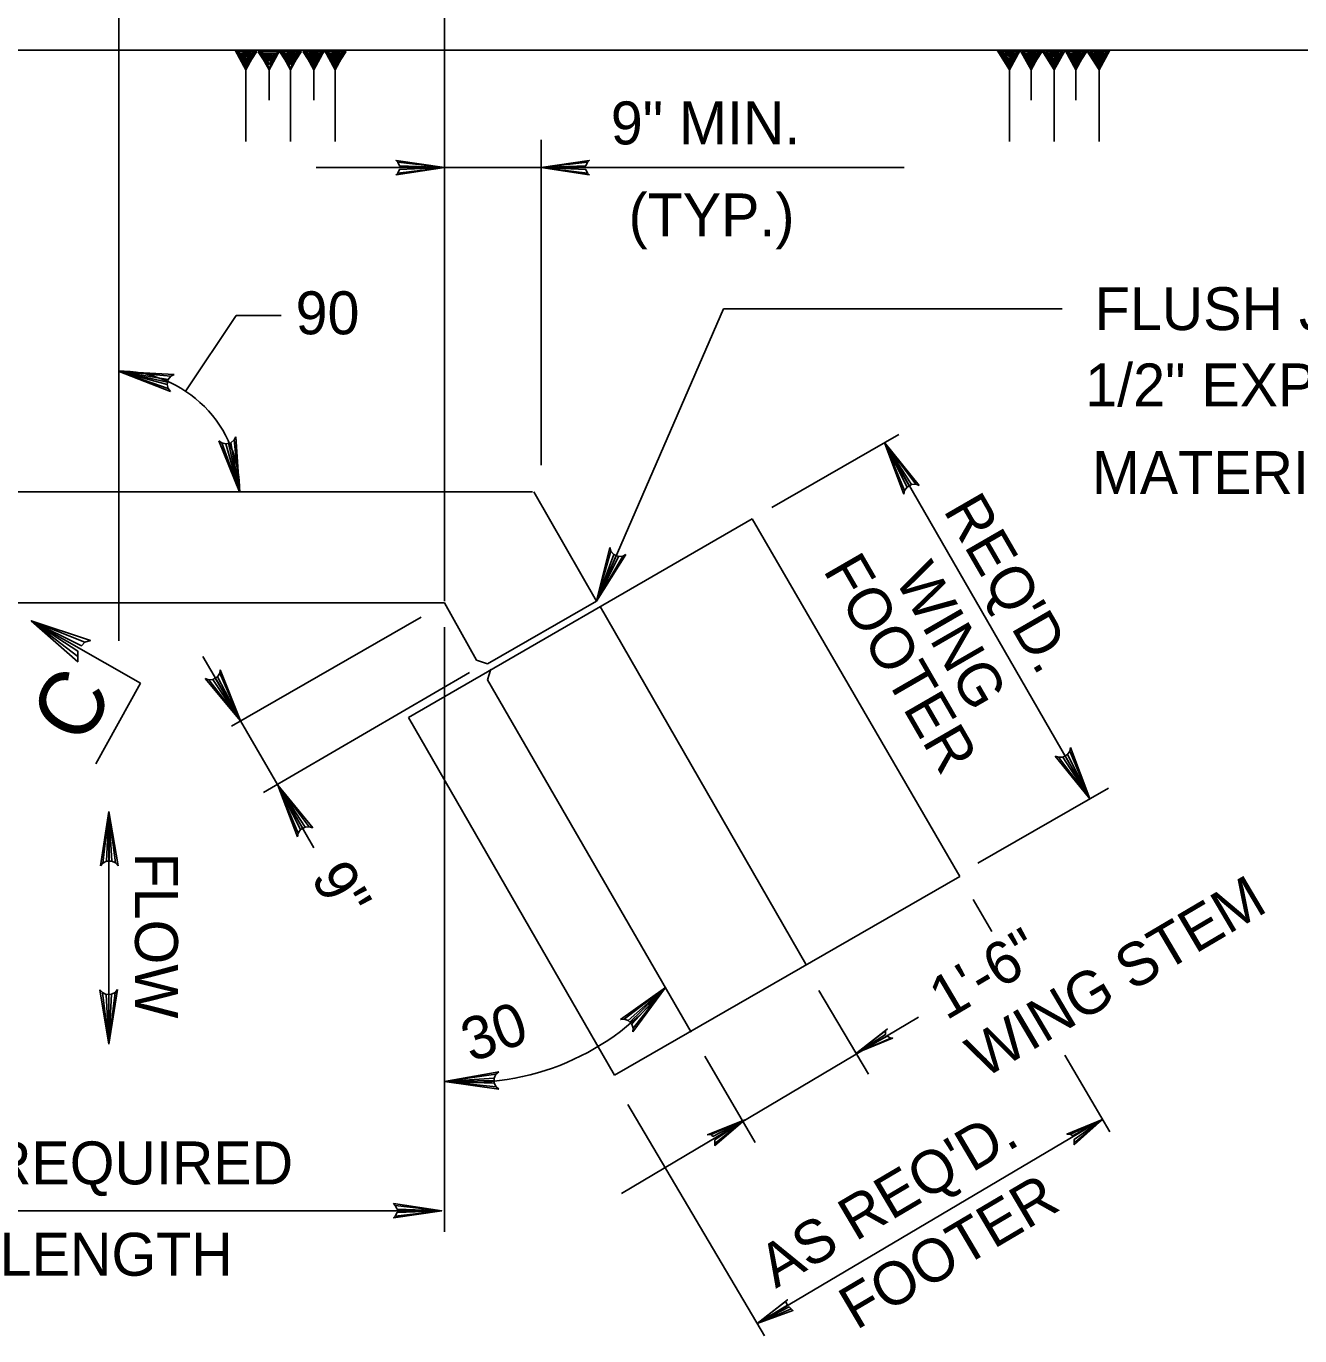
# Model space of a CAD drawing. Extents: x 639011 to 639866, y 298840 to 300028.
# Drawn here: x 639208.9 to 639297.8, y 299878.8 to 299970.3 of the extents above; entities that cross this region are included whole.
import ezdxf

# ---------------------------------------------------------------- set-up
doc = ezdxf.new("R2010")
doc.units = 0
doc.layers.add('2', color=7, linetype='Continuous')

msp = doc.modelspace()

# ---------------------------------------------------------------- linework, layer by layer
at = {"layer": '2'}
for p, q in [((639215.32, 299927.334), (639215.32, 300000.662)), ((639238.07, 299937.353), (639238.07, 299976.728)), ((639238.07, 299937.353), (639238.07, 299976.728)), ((639153.945, 299968.603), (639239.07, 299968.603)), ((639164.418, 299968.603), (639305.616, 299968.603)), ((639224.195, 299967.228), (639224.195, 299962.228)), ((639225.82, 299967.228), (639225.82, 299965.103)), ((639227.32, 299967.228), (639227.32, 299962.228)), ((639228.945, 299967.228), (639228.945, 299965.103)), ((639230.445, 299967.228), (639230.445, 299962.228)), ((639277.551, 299967.228), (639277.551, 299962.228)), ((639279.051, 299967.228), (639279.051, 299965.103)), ((639280.676, 299967.228), (639280.676, 299962.228)), ((639282.176, 299967.228), (639282.176, 299965.103)), ((639283.801, 299967.228), (639283.801, 299962.228)), ((639244.82, 299939.603), (639244.82, 299962.344)), ((639270.195, 299960.392), (639229.109, 299960.392)), ((639248.695, 299930.103), (639257.562, 299950.524)), ((639257.562, 299950.524), (639281.233, 299950.524)), ((639220.019, 299944.792), (639223.529, 299950.07)), ((639223.529, 299950.07), (639226.675, 299950.07)), ((639238.07, 299938.353), (639238.07, 299946.728)), ((639238.07, 299938.353), (639238.07, 299946.728)), ((639218.699, 299945.236), (639215.346, 299946.156)), ((639215.346, 299946.156), (639218.774, 299944.947)), ((639218.927, 299944.749), (639215.346, 299946.156)), ((639215.346, 299946.156), (639218.776, 299945.589)), ((639218.958, 299945.817), (639215.346, 299946.156)), ((639215.346, 299946.156), (639219.187, 299945.946)), ((639215.346, 299946.156), (639218.738, 299945.412)), ((639218.776, 299945.589), (639218.958, 299945.817)), ((639219.187, 299945.946), (639218.958, 299945.817)), ((639218.699, 299945.236), (639218.776, 299945.589)), ((639218.774, 299944.947), (639218.699, 299945.236)), ((639218.774, 299944.947), (639218.927, 299944.749)), ((639223.762, 299937.748), (639222.303, 299941.308)), ((639222.303, 299941.308), (639222.518, 299941.156)), ((639223.382, 299941.363), (639223.154, 299941.172)), ((639223.382, 299941.363), (639223.495, 299941.586)), ((639223.762, 299937.748), (639223.382, 299941.363)), ((639223.495, 299941.586), (639223.762, 299937.748)), ((639260.952, 299936.65), (639269.815, 299941.747)), ((639222.802, 299941.09), (639222.518, 299941.156)), ((639222.518, 299941.156), (639223.762, 299937.748)), ((639223.154, 299941.172), (639222.802, 299941.09)), ((639223.762, 299937.748), (639222.802, 299941.09)), ((639223.762, 299937.748), (639222.978, 299941.131)), ((639223.154, 299941.172), (639223.762, 299937.748)), ((639270.701, 299938.25), (639268.826, 299941.178)), ((639268.826, 299941.178), (639270.998, 299938.264)), ((639271.233, 299938.177), (639268.826, 299941.178)), ((639268.826, 299941.178), (639270.387, 299938.071)), ((639270.223, 299937.83), (639268.826, 299941.178)), ((639268.826, 299941.178), (639270.167, 299937.573)), ((639268.826, 299941.178), (639270.544, 299938.16)), ((639268.826, 299941.178), (639283.149, 299916.274)), ((639186.57, 299937.728), (639244.219, 299937.728)), ((639244.32, 299937.728), (639248.695, 299930.103)), ((639244.32, 299937.728), (639248.695, 299930.103)), ((639270.167, 299937.573), (639270.223, 299937.83)), ((639270.387, 299938.071), (639270.223, 299937.83)), ((639270.701, 299938.25), (639270.387, 299938.071)), ((639270.998, 299938.264), (639270.701, 299938.25)), ((639270.998, 299938.264), (639271.233, 299938.177)), ((639238.07, 299930.103), (639238.07, 299937.353)), ((639238.07, 299930.103), (639238.07, 299937.353)), ((639235.57, 299921.978), (639259.57, 299935.853)), ((639259.57, 299935.853), (639274.07, 299910.853)), ((639248.695, 299930.103), (639249.624, 299933.836)), ((639249.708, 299933.586), (639248.695, 299930.103)), ((639248.695, 299930.103), (639249.898, 299933.365)), ((639250.75, 299933.355), (639248.695, 299930.103)), ((639248.695, 299930.103), (639250.064, 299933.294)), ((639248.695, 299930.103), (639250.527, 299933.242)), ((639250.23, 299933.223), (639248.695, 299930.103)), ((639249.624, 299933.836), (639249.708, 299933.586)), ((639249.898, 299933.365), (639249.708, 299933.586)), ((639250.23, 299933.223), (639249.898, 299933.365)), ((639250.527, 299933.242), (639250.23, 299933.223)), ((639250.527, 299933.242), (639250.75, 299933.355)), ((639192.695, 299929.978), (639238.07, 299929.978)), ((639238.07, 299929.978), (639240.32, 299925.978)), ((639238.07, 299929.978), (639240.32, 299925.978)), ((639241.07, 299925.728), (639248.695, 299930.103)), ((639241.07, 299925.728), (639248.695, 299930.103)), ((639248.945, 299929.728), (639263.32, 299904.728)), ((639216.837, 299924.358), (639209.212, 299928.733)), ((639223.195, 299921.353), (639236.445, 299928.978)), ((639238.07, 299928.274), (639238.07, 299886.029)), ((639221.195, 299926.228), (639223.82, 299921.728)), ((639240.32, 299925.978), (639241.07, 299925.728)), ((639240.32, 299925.978), (639241.07, 299925.728)), ((639222.213, 299924.812), (639221.902, 299924.627)), ((639223.82, 299921.728), (639222.057, 299924.72)), ((639222.373, 299925.062), (639222.213, 299924.812)), ((639222.213, 299924.812), (639223.82, 299921.728)), ((639222.373, 299925.062), (639222.414, 299925.309)), ((639223.82, 299921.728), (639222.373, 299925.062)), ((639222.414, 299925.309), (639223.82, 299921.728)), ((639225.445, 299916.728), (639239.82, 299925.103)), ((639241.07, 299924.603), (639241.32, 299925.353)), ((639241.07, 299924.603), (639241.32, 299925.353)), ((639216.837, 299924.358), (639213.712, 299918.733)), ((639223.82, 299921.728), (639221.36, 299924.686)), ((639221.36, 299924.686), (639221.611, 299924.605)), ((639221.902, 299924.627), (639221.611, 299924.605)), ((639221.611, 299924.605), (639223.82, 299921.728)), ((639223.82, 299921.728), (639221.902, 299924.627)), ((639241.07, 299924.603), (639255.32, 299899.978)), ((639235.57, 299921.978), (639249.945, 299896.978)), ((639223.82, 299921.728), (639226.445, 299917.228)), ((639280.977, 299919.188), (639280.742, 299919.275)), ((639280.742, 299919.275), (639283.149, 299916.274)), ((639281.274, 299919.202), (639281.589, 299919.38)), ((639283.149, 299916.274), (639281.431, 299919.291)), ((639281.589, 299919.38), (639281.752, 299919.621)), ((639283.149, 299916.274), (639281.589, 299919.38)), ((639281.807, 299919.879), (639281.752, 299919.621)), ((639281.752, 299919.621), (639283.149, 299916.274)), ((639283.149, 299916.274), (639281.807, 299919.879)), ((639280.977, 299919.188), (639281.274, 299919.202)), ((639283.149, 299916.274), (639280.977, 299919.188)), ((639281.274, 299919.202), (639283.149, 299916.274)), ((639226.445, 299917.228), (639228.945, 299912.853)), ((639228.024, 299914.13), (639226.445, 299917.228)), ((639226.445, 299917.228), (639227.862, 299913.881)), ((639227.819, 299913.634), (639226.445, 299917.228)), ((639226.445, 299917.228), (639228.337, 299914.311)), ((639228.628, 299914.331), (639226.445, 299917.228)), ((639226.445, 299917.228), (639228.878, 299914.248)), ((639226.445, 299917.228), (639228.181, 299914.221)), ((639275.337, 299911.78), (639284.455, 299917.024)), ((639214.049, 299911.597), (639214.64, 299915.399)), ((639214.64, 299915.399), (639214.209, 299911.79)), ((639214.474, 299911.926), (639214.64, 299915.399)), ((639214.64, 299899.149), (639214.64, 299915.399)), ((639214.64, 299915.399), (639214.836, 299911.928)), ((639215.098, 299911.801), (639214.64, 299915.399)), ((639214.64, 299915.399), (639215.274, 299911.605)), ((639214.64, 299915.399), (639214.655, 299911.927)), ((639227.862, 299913.881), (639227.819, 299913.634)), ((639227.862, 299913.881), (639228.024, 299914.13)), ((639228.024, 299914.13), (639228.337, 299914.311)), ((639228.337, 299914.311), (639228.628, 299914.331)), ((639228.878, 299914.248), (639228.628, 299914.331)), ((639214.209, 299911.79), (639214.474, 299911.926)), ((639214.474, 299911.926), (639214.836, 299911.928)), ((639214.836, 299911.928), (639215.098, 299911.801)), ((639214.209, 299911.79), (639214.049, 299911.597)), ((639215.274, 299911.605), (639215.098, 299911.801)), ((639249.945, 299896.978), (639274.07, 299910.853)), ((639275.018, 299909.242), (639276.324, 299907.02)), ((639214.64, 299899.149), (639214.005, 299902.944)), ((639214.005, 299902.944), (639214.182, 299902.748)), ((639215.23, 299902.951), (639214.64, 299899.149)), ((639214.64, 299899.149), (639215.07, 299902.759)), ((639215.07, 299902.759), (639214.805, 299902.623)), ((639215.07, 299902.759), (639215.23, 299902.951)), ((639250.374, 299900.873), (639253.509, 299903.103)), ((639253.509, 299903.103), (639250.623, 299900.893)), ((639250.905, 299900.798), (639253.509, 299903.103)), ((639253.509, 299903.103), (639251.032, 299900.669)), ((639253.509, 299903.103), (639251.159, 299900.541)), ((639253.509, 299903.103), (639251.234, 299900.001)), ((639251.251, 299900.264), (639253.509, 299903.103)), ((639264.224, 299902.893), (639267.701, 299897.049)), ((639214.444, 299902.62), (639214.182, 299902.748)), ((639214.182, 299902.748), (639214.64, 299899.149)), ((639214.805, 299902.623), (639214.444, 299902.62)), ((639214.64, 299899.149), (639214.444, 299902.62)), ((639214.64, 299899.149), (639214.624, 299902.622)), ((639214.805, 299902.623), (639214.64, 299899.149)), ((639271.193, 299901.019), (639250.437, 299888.712)), ((639250.623, 299900.893), (639250.374, 299900.873)), ((639250.623, 299900.893), (639250.905, 299900.798)), ((639250.905, 299900.798), (639251.159, 299900.541)), ((639251.159, 299900.541), (639251.251, 299900.264)), ((639251.234, 299900.001), (639251.251, 299900.264)), ((639256.27, 299898.313), (639259.782, 299892.274)), ((639281.407, 299898.377), (639284.563, 299893.013)), ((639238.075, 299896.54), (639241.863, 299897.215)), ((639241.668, 299897.036), (639238.075, 299896.54)), ((639238.075, 299896.54), (639241.544, 299896.773)), ((639238.075, 299896.54), (639241.547, 299896.592)), ((639241.55, 299896.411), (639238.075, 299896.54)), ((639238.075, 299896.54), (639241.689, 299896.148)), ((639241.883, 299895.99), (639238.075, 299896.54)), ((639241.544, 299896.773), (639241.668, 299897.036)), ((639241.55, 299896.411), (639241.544, 299896.773)), ((639241.689, 299896.148), (639241.55, 299896.411)), ((639241.863, 299897.215), (639241.668, 299897.036)), ((639241.689, 299896.148), (639241.883, 299895.99)), ((639250.895, 299894.915), (639260.434, 299878.76)), ((639284.041, 299893.899), (639259.921, 299879.628)), ((639192.82, 299887.496), (639237.891, 299887.496))]:
    msp.add_line(p, q, dxfattribs=at)
for points in [[(639224.945, 299968.603), (639223.445, 299968.603), (639224.195, 299967.228)], [(639226.57, 299968.603), (639225.07, 299968.603), (639225.82, 299967.228)], [(639228.07, 299968.603), (639226.57, 299968.603), (639227.32, 299967.228)], [(639229.695, 299968.603), (639228.195, 299968.603), (639228.945, 299967.228)], [(639231.195, 299968.603), (639229.695, 299968.603), (639230.445, 299967.228)], [(639278.301, 299968.603), (639276.676, 299968.603), (639277.551, 299967.228)], [(639279.801, 299968.603), (639278.301, 299968.603), (639279.051, 299967.228)], [(639281.426, 299968.603), (639279.801, 299968.603), (639280.676, 299967.228)], [(639282.926, 299968.603), (639281.426, 299968.603), (639282.176, 299967.228)], [(639284.551, 299968.603), (639282.926, 299968.603), (639283.801, 299967.228)]]:
    msp.add_lwpolyline(points, close=True, dxfattribs=at)
for points in [[(639224.945, 299968.603), (639223.57, 299968.603), (639224.195, 299967.353), (639224.945, 299968.478), (639223.57, 299968.478), (639224.195, 299967.478), (639224.82, 299968.478), (639223.695, 299968.478), (639224.195, 299967.603), (639224.695, 299968.478), (639223.82, 299968.353), (639224.195, 299967.728), (639224.57, 299968.353), (639223.945, 299968.353), (639224.195, 299967.853), (639224.445, 299968.353), (639224.07, 299968.228), (639224.195, 299967.978), (639224.445, 299968.228), (639224.195, 299968.228), (639224.195, 299968.103), (639224.32, 299968.228)], [(639226.57, 299968.478), (639225.07, 299968.478), (639225.82, 299967.353), (639226.445, 299968.478), (639225.195, 299968.478), (639225.82, 299967.353), (639226.445, 299968.478), (639225.32, 299968.478), (639225.82, 299967.603), (639226.32, 299968.353), (639225.445, 299968.353), (639225.82, 299967.603), (639226.195, 299968.353), (639225.57, 299968.353), (639225.82, 299967.853), (639226.07, 299968.228), (639225.695, 299968.228), (639225.82, 299967.978), (639225.945, 299968.228), (639225.695, 299968.228), (639225.82, 299968.103), (639225.82, 299968.228)], [(639228.07, 299968.478), (639226.57, 299968.478), (639227.32, 299967.353), (639228.07, 299968.478), (639226.695, 299968.478), (639227.32, 299967.353), (639227.945, 299968.478), (639226.82, 299968.478), (639227.32, 299967.603), (639227.82, 299968.478), (639226.945, 299968.353), (639227.32, 299967.728), (639227.695, 299968.353), (639227.07, 299968.353), (639227.32, 299967.853), (639227.57, 299968.353), (639227.195, 299968.228), (639227.32, 299967.978), (639227.445, 299968.228), (639227.32, 299968.228), (639227.32, 299968.103), (639227.445, 299968.228)], [(639229.695, 299968.478), (639228.195, 299968.478), (639228.945, 299967.353), (639229.57, 299968.478), (639228.32, 299968.478), (639228.945, 299967.478), (639229.57, 299968.478), (639228.445, 299968.478), (639228.945, 299967.603), (639229.445, 299968.478), (639228.445, 299968.353), (639228.945, 299967.728), (639229.32, 299968.353), (639228.57, 299968.353), (639228.945, 299967.853), (639229.195, 299968.353), (639228.695, 299968.228), (639228.945, 299967.978), (639229.07, 299968.228), (639228.82, 299968.228), (639228.945, 299968.103), (639228.945, 299968.228)], [(639231.195, 299968.603), (639229.82, 299968.478), (639230.445, 299967.353), (639231.195, 299968.478), (639229.82, 299968.478), (639230.445, 299967.478), (639231.07, 299968.478), (639229.945, 299968.478), (639230.445, 299967.603), (639230.945, 299968.478), (639230.07, 299968.353), (639230.445, 299967.728), (639230.82, 299968.353), (639230.195, 299968.353), (639230.445, 299967.853), (639230.695, 299968.353), (639230.32, 299968.228), (639230.445, 299967.978), (639230.695, 299968.228), (639230.445, 299968.228), (639230.445, 299968.103), (639230.57, 299968.228)], [(639278.301, 299968.603), (639276.801, 299968.603), (639277.551, 299967.353), (639278.176, 299968.603), (639276.926, 299968.478), (639277.551, 299967.478), (639278.176, 299968.478), (639277.051, 299968.478), (639277.551, 299967.603), (639278.051, 299968.478), (639277.051, 299968.353), (639277.551, 299967.728), (639277.926, 299968.353), (639277.176, 299968.353), (639277.551, 299967.853), (639277.801, 299968.353), (639277.301, 299968.228), (639277.551, 299967.978), (639277.676, 299968.228), (639277.426, 299968.228), (639277.551, 299968.103), (639277.551, 299968.228)], [(639279.801, 299968.603), (639278.426, 299968.478), (639279.051, 299967.353), (639279.801, 299968.478), (639278.426, 299968.478), (639279.051, 299967.478), (639279.676, 299968.478), (639278.551, 299968.478), (639279.051, 299967.603), (639279.551, 299968.478), (639278.676, 299968.353), (639279.051, 299967.728), (639279.426, 299968.353), (639278.801, 299968.353), (639279.051, 299967.853), (639279.301, 299968.353), (639278.926, 299968.228), (639279.051, 299967.978), (639279.176, 299968.228), (639279.051, 299968.228), (639279.051, 299968.103), (639279.176, 299968.228)], [(639281.301, 299968.603), (639279.926, 299968.603), (639280.676, 299967.353), (639281.301, 299968.478), (639280.051, 299968.478), (639280.676, 299967.478), (639281.176, 299968.478), (639280.176, 299968.478), (639280.676, 299967.603), (639281.176, 299968.478), (639280.176, 299968.353), (639280.676, 299967.728), (639281.051, 299968.353), (639280.301, 299968.353), (639280.676, 299967.853), (639280.926, 299968.353), (639280.426, 299968.228), (639280.676, 299967.978), (639280.801, 299968.228), (639280.551, 299968.228), (639280.676, 299968.103), (639280.676, 299968.228)], [(639282.926, 299968.603), (639281.426, 299968.603), (639282.176, 299967.353), (639282.926, 299968.478), (639281.551, 299968.478), (639282.176, 299967.478), (639282.801, 299968.478), (639281.676, 299968.478), (639282.176, 299967.603), (639282.676, 299968.478), (639281.801, 299968.353), (639282.176, 299967.728), (639282.551, 299968.353), (639281.926, 299968.353), (639282.176, 299967.853), (639282.426, 299968.353), (639282.051, 299968.228), (639282.176, 299967.978), (639282.301, 299968.228), (639282.176, 299968.228), (639282.176, 299968.103), (639282.301, 299968.228)], [(639284.426, 299968.603), (639283.051, 299968.603), (639283.801, 299967.353), (639284.426, 299968.603), (639283.176, 299968.478), (639283.801, 299967.478), (639284.301, 299968.478), (639283.301, 299968.478), (639283.801, 299967.603), (639284.301, 299968.478), (639283.301, 299968.353), (639283.801, 299967.728), (639284.176, 299968.353), (639283.426, 299968.353), (639283.801, 299967.853), (639284.051, 299968.353), (639283.551, 299968.228), (639283.801, 299967.978), (639283.926, 299968.228), (639283.676, 299968.228), (639283.801, 299968.103), (639283.801, 299968.228)], [(639234.82, 299960.017), (639234.945, 299960.267), (639238.07, 299960.392), (639234.82, 299960.017), (639234.695, 299959.892), (639238.07, 299960.392), (639234.945, 299960.517), (639234.82, 299960.767), (639238.07, 299960.392), (639234.695, 299960.892), (639234.82, 299960.767)], [(639248.07, 299960.017), (639247.945, 299960.267), (639244.82, 299960.392), (639248.07, 299960.017), (639248.195, 299959.892), (639244.82, 299960.392), (639247.945, 299960.517), (639248.07, 299960.767), (639244.82, 299960.392), (639248.195, 299960.892), (639248.07, 299960.767)], [(639212.462, 299926.233), (639212.462, 299926.608), (639209.212, 299928.733), (639212.462, 299926.233), (639212.462, 299925.858), (639209.212, 299928.733), (639212.712, 299926.983), (639212.962, 299927.233), (639209.212, 299928.733), (639213.337, 299927.358), (639212.962, 299927.233)], [(639268.878, 299900.065), (639268.88, 299899.815), (639266.893, 299898.545), (639268.878, 299900.065), (639269.002, 299900.191), (639266.893, 299898.545), (639269.007, 299899.691), (639269.258, 299899.569), (639266.893, 299898.545), (639269.383, 299899.57), (639269.258, 299899.569)], [(639268.878, 299900.065), (639268.88, 299899.815), (639266.893, 299898.545), (639268.878, 299900.065), (639269.002, 299900.191), (639266.893, 299898.545), (639269.007, 299899.691), (639269.258, 299899.569), (639266.893, 299898.545), (639269.383, 299899.57), (639269.258, 299899.569)], [(639256.957, 299892.194), (639256.954, 299892.444), (639259.065, 299893.841), (639256.957, 299892.194), (639256.958, 299892.069), (639259.065, 299893.841), (639256.827, 299892.693), (639256.701, 299892.817), (639259.065, 299893.841), (639256.451, 299892.814), (639256.701, 299892.817)], [(639256.957, 299892.194), (639256.954, 299892.444), (639259.065, 299893.841), (639256.957, 299892.194), (639256.958, 299892.069), (639259.065, 299893.841), (639256.827, 299892.693), (639256.701, 299892.817), (639259.065, 299893.841), (639256.451, 299892.814), (639256.701, 299892.817)], [(639282.07, 299892.237), (639282.068, 299892.487), (639284.054, 299893.883), (639282.07, 299892.237), (639282.071, 299892.112), (639284.054, 299893.883), (639281.94, 299892.736), (639281.814, 299892.86), (639284.054, 299893.883), (639281.564, 299892.857), (639281.814, 299892.86)], [(639282.07, 299892.237), (639282.068, 299892.487), (639284.054, 299893.883), (639282.07, 299892.237), (639282.071, 299892.112), (639284.054, 299893.883), (639281.94, 299892.736), (639281.814, 299892.86), (639284.054, 299893.883), (639281.564, 299892.857), (639281.814, 299892.86)], [(639234.641, 299887.121), (639234.766, 299887.371), (639237.891, 299887.496), (639234.641, 299887.121), (639234.516, 299886.996), (639237.891, 299887.496), (639234.766, 299887.621), (639234.641, 299887.871), (639237.891, 299887.496), (639234.516, 299887.996), (639234.641, 299887.871)], [(639261.91, 299881.15), (639262.037, 299880.901), (639259.925, 299879.63), (639261.91, 299881.15), (639262.033, 299881.276), (639259.925, 299879.63), (639262.163, 299880.778), (639262.289, 299880.654), (639259.925, 299879.63), (639262.416, 299880.53), (639262.289, 299880.654)], [(639261.91, 299881.15), (639262.037, 299880.901), (639259.925, 299879.63), (639261.91, 299881.15), (639262.033, 299881.276), (639259.925, 299879.63), (639262.163, 299880.778), (639262.289, 299880.654), (639259.925, 299879.63), (639262.416, 299880.53), (639262.289, 299880.654)]]:
    msp.add_lwpolyline(points, dxfattribs=at)
for centre, radius, start, end in [((639215.32, 299937.728), 8.45, 359.68483, 90.21398), ((639239.746, 299914.039), 17.579, 264.54493, 321.52843)]:
    msp.add_arc(centre, radius, start, end, dxfattribs=at)

# ---------------------------------------------------------------- texts
for s, p in [('9" MIN.', (639249.694, 299962.017)), ('(TYP.)', (639250.939, 299955.587)), ('90', (639227.676, 299948.747)), ('FLUSH JOINT WITH', (639283.501, 299949.039)), ('1/2" EXPANSION JOINT', (639282.84, 299943.708)), ('MATERIAL (TYP.)', (639283.308, 299937.588)), ('AS REQUIRED', (639199.86, 299889.342)), ('LENGTH', (639207.008, 299882.958))]:
    msp.add_text(s, height=3, dxfattribs=at).set_placement(p)
for s, height, rotation, p in [("REQ'D.", 3, 300.01947, (639272.883, 299936.457)), ('FOOTER', 3, 300.01947, (639264.485, 299932.265)), ('WING', 3, 300.01947, (639269.469, 299931.661)), ('C', 4.5, 60.01591, (639212.837, 299919.858)), ('FLOW', 3, 270, (639216.457, 299912.524)), ('9"', 3, 300.00248, (639228.69, 299910.789)), ('WING STEM', 3, 30.57625, (639275.742, 299896.692)), ('1\'-6"', 3, 30.57625, (639273.128, 299900.771)), ('30', 3, 20, (639239.945, 299897.853)), ("AS REQ'D.", 3, 30.57625, (639261.218, 299882.037)), ('FOOTER', 3, 30.57625, (639266.846, 299879.129))]:
    msp.add_text(s, height=height, rotation=rotation, dxfattribs=at).set_placement(p)

doc.saveas('drawing.dxf')
